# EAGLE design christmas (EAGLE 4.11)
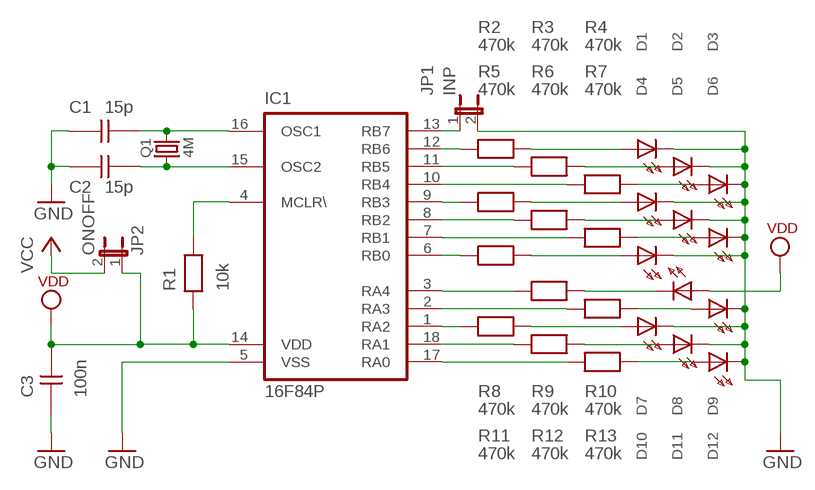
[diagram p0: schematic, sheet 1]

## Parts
C1  15p  CAPNP-2,5  [C-2,5]
C2  15p  CAPNP-2,5  [C-2,5]
C3  100n  CAPNP-7,5  [C-7,5]
D1  LED2  [LED2]
D2  LED2  [LED2]
D3  LED2  [LED2]
D4  LED2  [LED2]
D5  LED2  [LED2]
D6  LED2  [LED2]
D7  LED2  [LED2]
D8  LED2  [LED2]
D9  LED2  [LED2]
D10  LED2  [LED2]
D11  LED2  [LED2]
D12  LED2  [LED2]
IC1  16F84P  [DIL18]
JP1  INP  JP1E  [JP1]
JP2  ONOFF  JP1E  [JP1]
Q1  4M  HC18U-V  [HC18U-V]
R1  10k  RESEU-7,5  [R-7,5]
R2  470k  RESEU-7,5  [R-7,5]
R3  470k  RESEU-7,5  [R-7,5]
R4  470k  RESEU-7,5  [R-7,5]
R5  470k  RESEU-7,5  [R-7,5]
R6  470k  RESEU-7,5  [R-7,5]
R7  470k  RESEU-7,5  [R-7,5]
R8  470k  RESEU-7,5  [R-7,5]
R9  470k  RESEU-7,5  [R-7,5]
R10  470k  RESEU-7,5  [R-7,5]
R11  470k  RESEU-7,5  [R-7,5]
R12  470k  RESEU-7,5  [R-7,5]
R13  470k  RESEU-7,5  [R-7,5]

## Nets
GND: C1.1 C2.1 C3.1 D1.K D2.K D3.K D4.K D5.K D6.K D7.K D9.K D10.K D11.K D12.K IC1.5(VSS) JP1.2
MCLR: IC1.4(MCLR\) R1.2
N$1: IC1.12(RB6) R2.1
N$4: IC1.11(RB5) R3.1
N$6: IC1.10(RB4) R4.1
N$7: IC1.9(RB3) R5.1
N$8: D1.A R2.2
N$9: IC1.8(RB2) R6.1
N$10: IC1.7(RB1) R7.1
N$11: D2.A R3.2
N$12: IC1.6(RB0) R8.1
N$13: IC1.3(RA4) R9.1
N$14: D3.A R4.2
N$15: IC1.2(RA3) R10.1
N$16: IC1.1(RA2) R11.1
N$17: D4.A R5.2
N$18: IC1.18(RA1) R12.1
N$19: IC1.17(RA0) R13.1
N$20: D6.A R7.2
N$21: IC1.13(RB7) JP1.1
N$23: D5.A R6.2
N$25: D8.K R9.2
N$26: D7.A R8.2
N$32: D9.A R10.2
N$35: D10.A R11.2
N$38: D11.A R12.2
N$41: D12.A R13.2
OSC1: C1.2 IC1.16(OSC1) Q1.2
OSC2: C2.2 IC1.15(OSC2) Q1.1
VCC: JP2.2
VDD: C3.2 D8.A IC1.14(VDD) JP2.1 R1.1

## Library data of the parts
C1 C2 = DISCRETE:CAPNP-2,5
C3 = DISCRETE:CAPNP-7,5
D1-D12 = LED:LED2
IC1 = PIC:16F84P
JP1 JP2 = JUMPS:JP1E
Q1 = QUARTZ:HC18U-V
R1-R13 = DISCRETE:RESEU-7,5

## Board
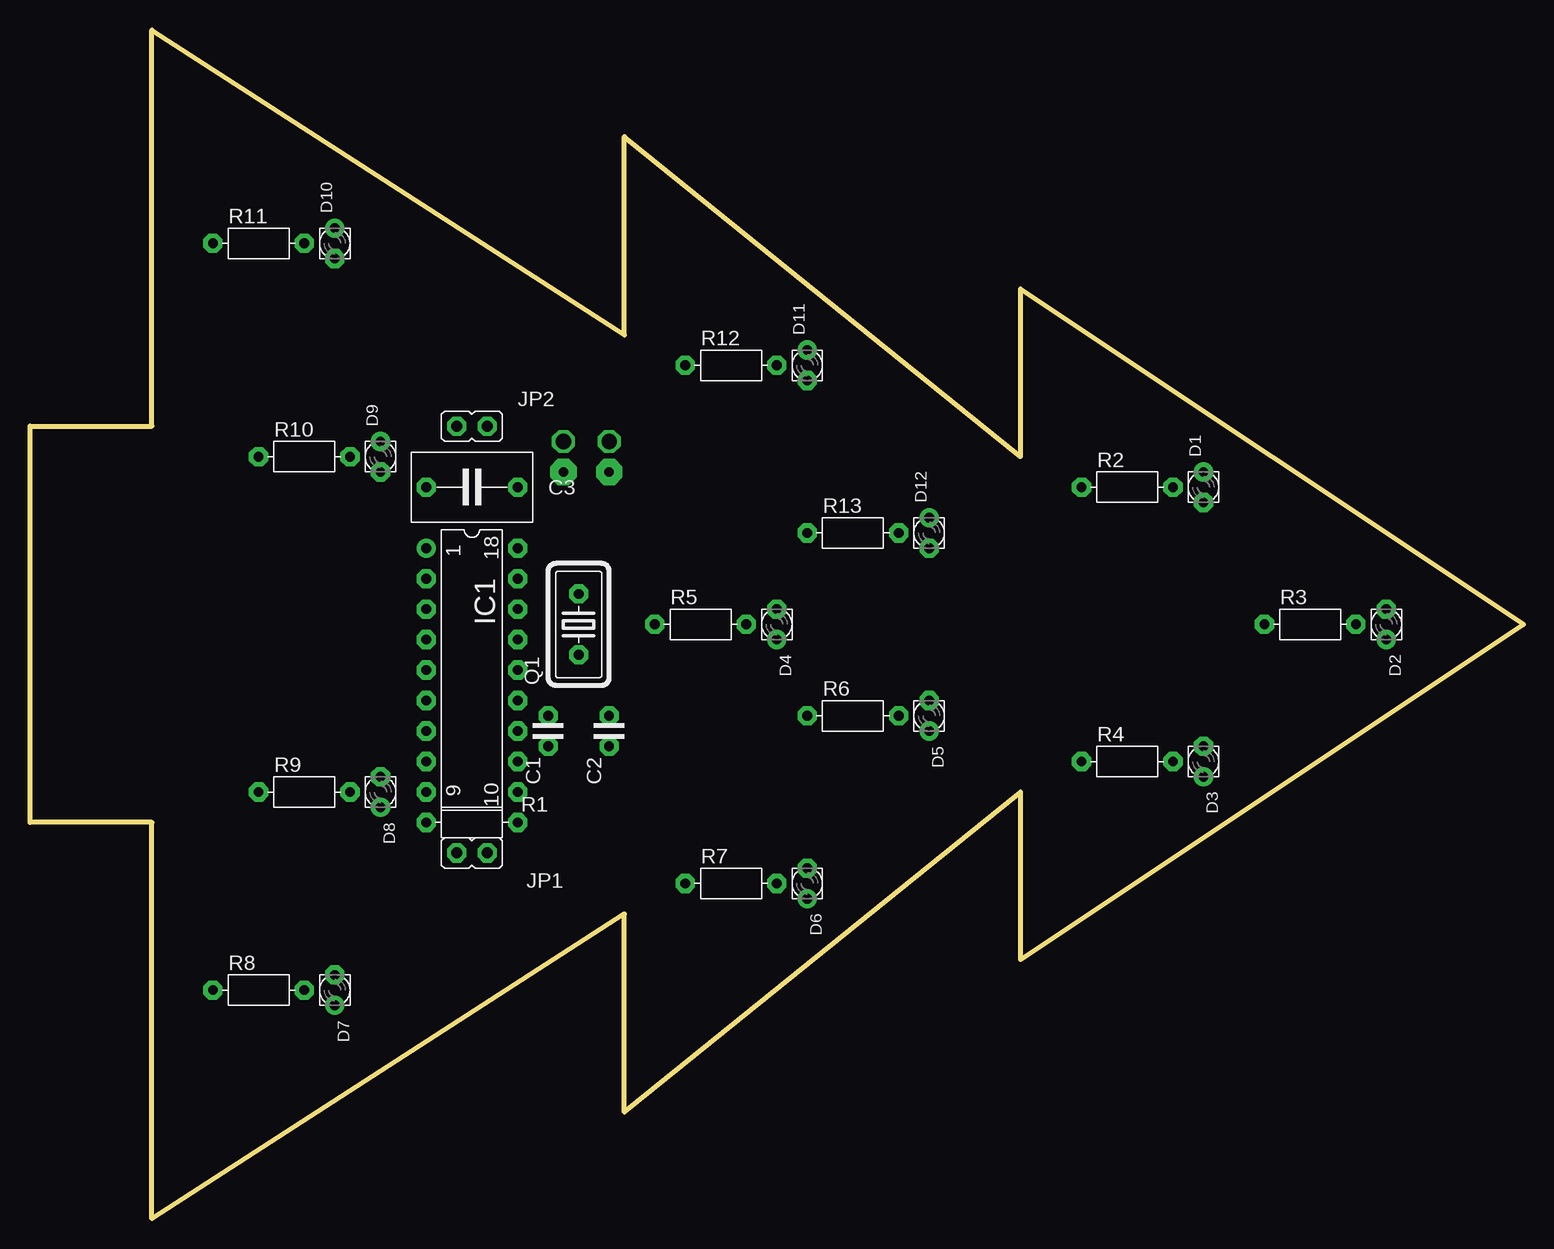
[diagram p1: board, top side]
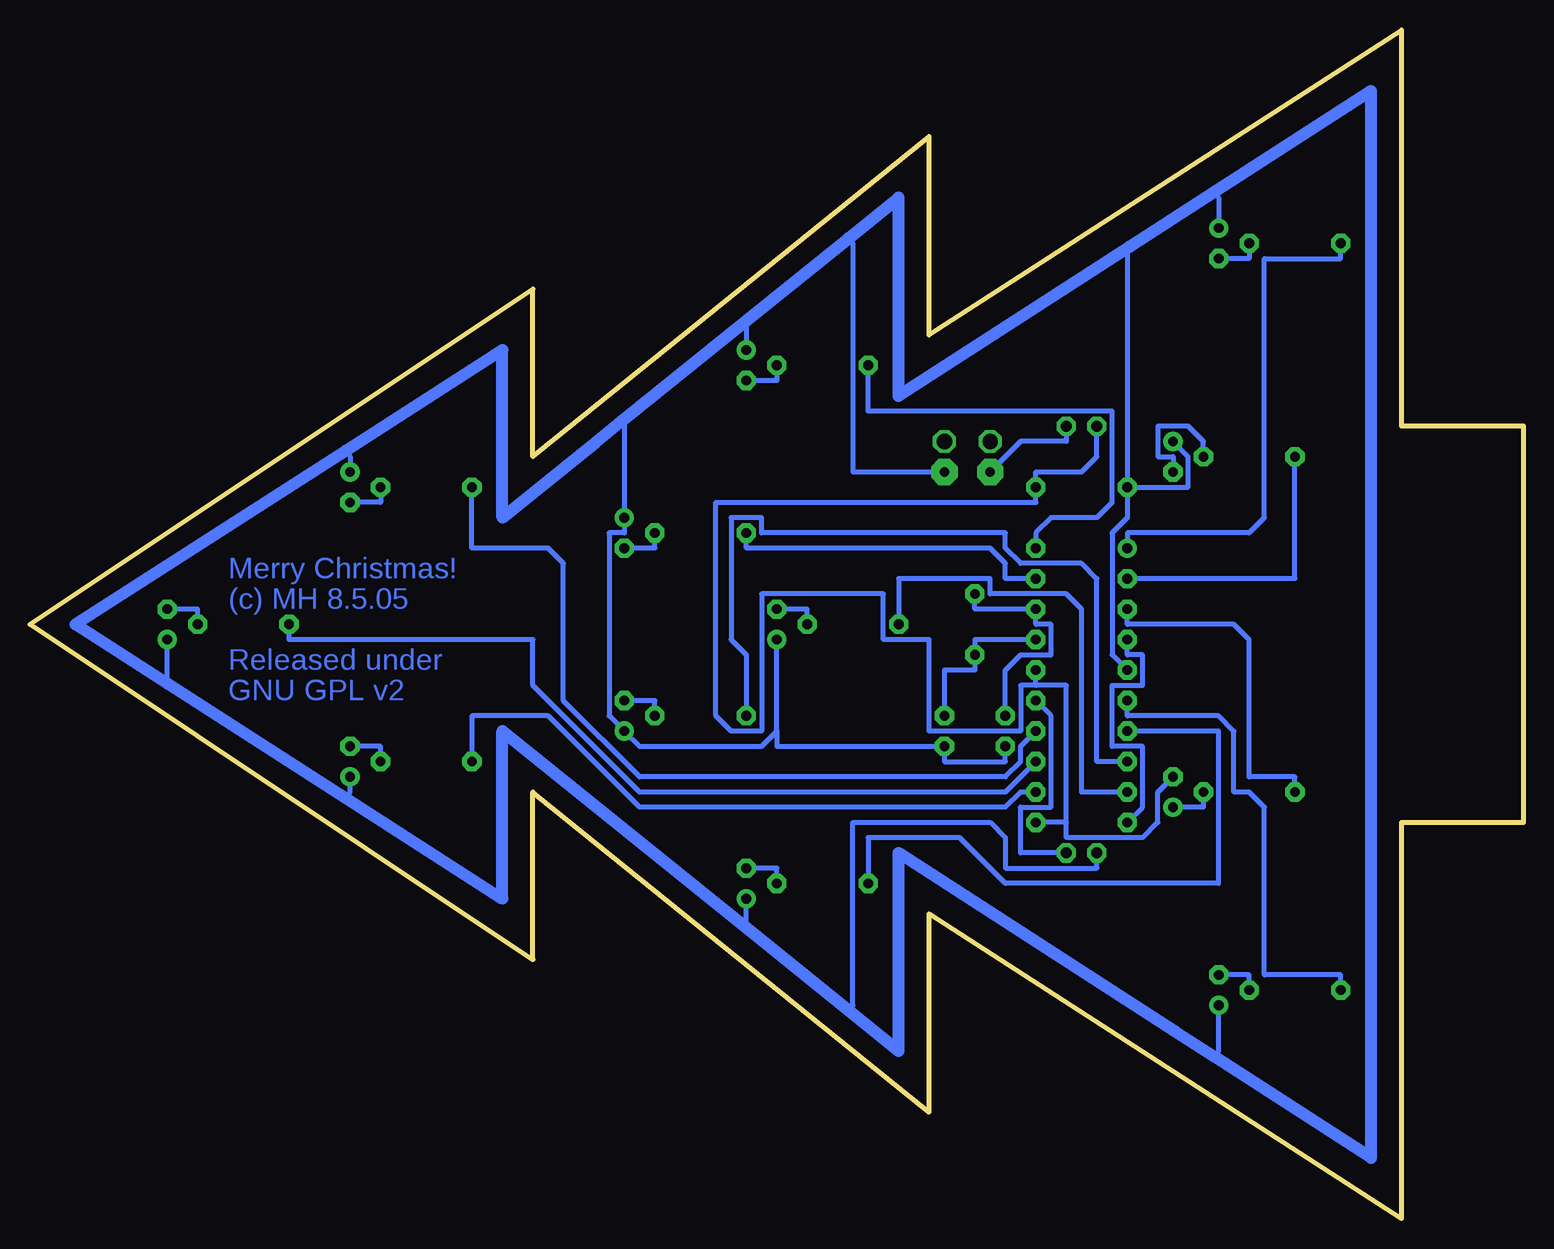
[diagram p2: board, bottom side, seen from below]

Size 124.46 x 99.06 mm. Coordinates in mm from the lower left corner, seen from the top.
Outline: 10.16,99.06 49.53,73.66 49.53,90.17 82.55,63.5 82.55,77.47 124.46,49.53 82.55,21.59 82.55,35.56 49.53,8.89 49.53,25.4 10.16,0 10.16,33.02 0,33.02 0,66.04 10.16,66.04 10.16,99.06
Copper layers (1*16): Top 0.035mm / dielectric 1.5mm / Bottom 0.035mm
Design rules "default": minimum track width 10mil, minimum drill 24mil, track to track 8mil, track to pad 8mil, pad to pad 8mil, via to via 8mil, smd to smd 8mil, copper to edge 40mil, drill to drill 8mil, minimum pad ring 10mil, minimum via ring 8mil, stop-mask expansion 4mil, vias tented up to drill 0mil, thermal gap 10mil

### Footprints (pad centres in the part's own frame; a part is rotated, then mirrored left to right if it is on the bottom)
C-2,5 = drill 0.813 pad 1.6 octagon: 1 -1.27,0; 2 1.27,0
C-7,5 = drill 0.813 pad 1.6 octagon: 1 -3.81,0; 2 3.81,0
LED2 = drill 0.813 pad 1.6 octagon: A -1.27,0 | drill 0.813 pad 1.6 round: K 1.27,0
DIL18 = drill 0.813 pad 1.6 round: 1 -10.16,-3.81 | drill 0.813 pad 1.6 octagon: 2 -7.62,-3.81; 3 -5.08,-3.81; 4 -2.54,-3.81; 5 0,-3.81; 6 2.54,-3.81; 7 5.08,-3.81; 8 7.62,-3.81; 9 10.16,-3.81; 10 10.16,3.81; 11 7.62,3.81; 12 5.08,3.81; 13 2.54,3.81; 14 0,3.81; 15 -2.54,3.81; 16 -5.08,3.81; 17 -7.62,3.81; 18 -10.16,3.81
JP1 = drill 0.914 pad 1.6 octagon: 1 0,-1.27; 2 0,1.27
HC18U-V = drill 0.813 pad 1.6 octagon: 1 -2.54,0; 2 2.54,0
R-7,5 = drill 0.813 pad 1.6 octagon: 1 -3.81,0; 2 3.81,0

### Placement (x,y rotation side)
C1  43.18,40.64 90 top
C2  48.26,40.64 90 top
C3  36.83,60.96 0 top
D1  97.79,60.96 90 top
D2  113.03,49.53 270 top
D3  97.79,38.1 270 top
D4  62.23,49.53 270 top
D5  74.93,41.91 270 top
D6  64.77,27.94 270 top
D7  25.4,19.05 270 top
D8  29.21,35.56 270 top
D9  29.21,63.5 90 top
D10  25.4,81.28 90 top
D11  64.77,71.12 90 top
D12  74.93,57.15 90 top
IC1  36.83,45.72 270 top
JP1  36.83,30.48 90 top
JP2  36.83,66.04 270 top
Q1  45.72,49.53 90 top
R1  36.83,33.02 180 top
R2  91.44,60.96 0 top
R3  106.68,49.53 0 top
R4  91.44,38.1 0 top
R5  55.88,49.53 0 top
R6  68.58,41.91 0 top
R7  58.42,27.94 0 top
R8  19.05,19.05 0 top
R9  22.86,35.56 0 top
R10  22.86,63.5 0 top
R11  19.05,81.28 0 top
R12  58.42,71.12 0 top
R13  68.58,57.15 0 top

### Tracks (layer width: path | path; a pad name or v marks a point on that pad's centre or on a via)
GND  (via drill 0.81 pad 2.18)
  Bottom 0.406: D6.K 64.77,24.13 64.72,24.19 | 77.37,64.65 77.47,64.77 | D3.K 97.79,35.56 98.12,35.05 | D11.K 64.77,74.93 64.72,74.87 | D10.K 25.4,85.09 25.72,85.58 | D2.K 113.03,44.45 112.95,44.58 | C1.1 43.18,38.1 48.26,38.1 C2.1 62.23,39.37 62.23,40.64 | 62.23,40.64 D4.K | 62.23,40.64 63.5,39.37 73.66,39.37 D5.K 76.2,41.91 76.2,57.15 74.93,57.15 D12.K 74.93,66.04 75.22,66.4 | IC1.5 34.29,46.99 34.29,57.15 33.02,58.42 C3.1 | D9.K 27.94,63.5 27.94,60.96 C3.1 | D7.K 25.4,13.97 25.72,13.48 | D1.K 97.79,63.5 98.12,64.01 | C3.1 33.02,81.28 32.83,80.99 | JP1.2 35.56,29.21 43.18,29.21 43.18,31.75 44.45,33.02 55.88,33.02 55.88,17.78 56.24,17.34 | v48.26,62.23 55.88,62.23 55.88,81.28 56.24,81.72
  Bottom 1.016: 25.72,85.58 12.7,93.98 12.7,5.08 25.72,13.48 28.99,15.59 52.07,30.48 52.07,13.97 56.24,17.34 | 25.72,85.58 | 25.72,85.58 32.83,80.99 52.07,68.58 52.07,85.09 56.24,81.72 64.72,74.87 75.22,66.4 77.37,64.65 85.09,58.42 85.09,72.39 98.12,64.01 120.65,49.53 112.95,44.58 98.12,35.05 85.09,26.67 85.09,40.64 64.72,24.19 56.24,17.34 | 56.24,17.34
MCLR
  Bottom 0.406: R1.2 31.75,34.29 31.75,39.37 34.29,39.37 34.29,44.45 31.75,44.45 31.75,46.99 33.02,46.99 IC1.4
N$1
  Bottom 0.406: IC1.12 41.91,39.37 41.91,38.1 43.18,36.83 73.66,36.83 80.01,43.18 80.01,54.61 81.28,55.88 87.63,55.88 R2.1
N$4
  Bottom 0.406: IC1.11 43.18,35.56 73.66,35.56 82.55,44.45 82.55,48.26 102.87,48.26 R3.1
N$6
  Bottom 0.406: IC1.10 41.91,35.56 43.18,34.29 73.66,34.29 81.28,41.91 87.63,41.91 R4.1
N$7
  Bottom 0.406: IC1.9 36.83,35.56 36.83,50.8 38.1,52.07 44.45,52.07 44.45,53.34 52.07,53.34 R5.1
N$8
  Bottom 0.406: R2.2 95.25,59.69 D1.A
N$9
  Bottom 0.406: IC1.8 35.56,38.1 35.56,53.34 36.83,54.61 41.91,54.61 43.18,55.88 43.18,57.15 63.5,57.15 63.5,58.42 66.04,58.42 66.04,48.26 64.77,46.99 R6.1
N$10
  Bottom 0.406: IC1.7 25.4,40.64 25.4,27.94 43.18,27.94 46.99,31.75 54.61,31.75 R7.1
N$11
  Bottom 0.406: R3.2 110.49,50.8 D2.A
N$12
  Bottom 0.406: R8.1 15.24,20.32 21.59,20.32 21.59,34.29 22.86,35.56 24.13,35.56 24.13,40.64 25.4,41.91 33.02,41.91 IC1.6
N$13
  Bottom 0.406: R9.1 19.05,36.83 22.86,36.83 22.86,48.26 24.13,49.53 33.02,49.53 IC1.3
N$14
  Bottom 0.406: R4.2 95.25,39.37 D3.A
N$15
  Bottom 0.406: IC1.2 19.05,53.34 R10.1
N$16
  Bottom 0.406: R11.1 15.24,80.01 21.59,80.01 21.59,58.42 22.86,57.15 33.02,57.15 IC1.1
N$17
  Bottom 0.406: R5.2 59.69,50.8 D4.A
N$18
  Bottom 0.406: IC1.18 40.64,57.15 39.37,58.42 35.56,58.42 34.29,59.69 34.29,67.31 54.61,67.31 R12.1
N$19
  Bottom 0.406: IC1.17 43.18,53.34 43.18,54.61 44.45,55.88 64.77,55.88 R13.1
N$20
  Bottom 0.406: R7.2 62.23,29.21 D6.A
N$21
  Bottom 0.406: IC1.13 39.37,41.91 39.37,34.29 41.91,34.29 41.91,30.48 JP1.1
N$23
  Bottom 0.406: R6.2 72.39,43.18 D5.A
N$25
  Bottom 0.406: R9.2 26.67,34.29 D8.K
N$26
  Bottom 0.406: R8.2 22.86,20.32 D7.A
N$27  (via drill 1.27 pad 1.6)
  other vias: 44.45,64.77
N$28  (via drill 1.27 pad 1.6)
  other vias: 48.26,64.77
N$32
  Bottom 0.406: R10.2 26.67,64.77 27.94,66.04 30.48,66.04 30.48,63.5 29.21,63.5 D9.A
N$35
  Bottom 0.406: R11.2 22.86,80.01 D10.A
N$38
  Bottom 0.406: R12.2 62.23,69.85 D11.A
N$41
  Bottom 0.406: D12.A 72.39,55.88 R13.2
OSC1
  Bottom 0.406: C1.2 43.18,45.72 41.91,46.99 39.37,46.99 39.37,49.53 40.64,49.53 IC1.16 45.72,50.8 Q1.2
OSC2
  Bottom 0.406: C2.2 48.26,45.72 45.72,45.72 Q1.1 45.72,48.26 IC1.15
VCC  (via drill 0.81 pad 2.18)
  Bottom 0.406: JP2.2 38.1,64.77 41.91,64.77 v44.45,62.23
VDD
  Bottom 0.406: 38.1,33.02 R1.1 | 38.1,33.02 38.1,44.45 40.64,44.45 | 40.64,44.45 IC1.14 | 40.64,44.45 41.91,44.45 41.91,40.64 49.53,40.64 49.53,48.26 53.34,48.26 53.34,52.07 63.5,52.07 63.5,40.64 66.04,40.64 67.31,41.91 67.31,59.69 40.64,59.69 C3.2 40.64,62.23 36.83,62.23 35.56,63.5 JP2.1 | D8.A 30.48,35.56 30.48,33.02 31.75,31.75 38.1,31.75 38.1,33.02

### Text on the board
Bottom: Merry Christmas! | (c) MH 8.5.05 | Released under | GNU GPL v2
